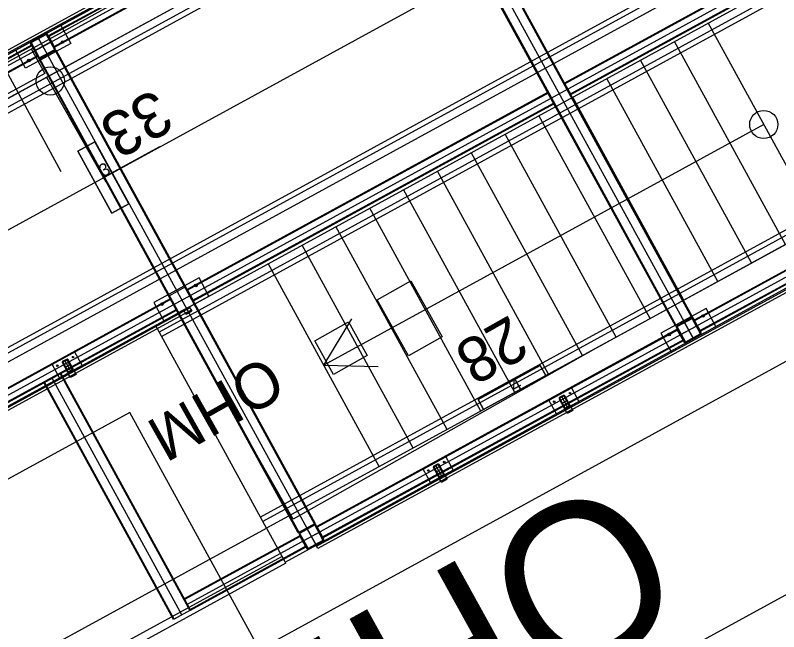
# Model space of a CAD drawing. Extents: x -783978 to -783565, y -1064821 to -1064596.
# Drawn here: x -783747.19 to -783741.25, y -1064675.51 to -1064670.72 of the extents above; entities that cross this region are included whole.
import ezdxf

# ---------------------------------------------------------------- set-up
doc = ezdxf.new("R2010")
doc.units = 0
for name, color, linetype in [('Default', 7, 'Continuous'), ('SO 01_20_01', 7, 'Continuous'), ('SO 01_50_01', 7, 'Continuous'), ('SO 01_74_01', 7, 'Continuous'), ('SO 01_77_01', 7, 'Continuous'), ('SO 01_79_02', 7, 'Continuous'), ('SO 01_86_04', 7, 'Continuous')]:
    doc.layers.add(name, color=color, linetype=linetype)

# ---------------------------------------------------------------- blocks, each defined once
blk = doc.blocks.new('POINT_DISPLAY')
at = {"layer": 'Default'}
blk.add_line((0, 0), (0, 0), dxfattribs=at)

msp = doc.modelspace()

# ---------------------------------------------------------------- linework, layer by layer
at = {"layer": 'SO 01_20_01'}
for p, q in [((-783735.2041, -1064664.4318), (-783786.7885, -1064692.6541)), ((-783786.6445, -1064692.9173), (-783735.3233, -1064664.839)), ((-783738.0171, -1064666.3812), (-783786.4402, -1064692.874)), ((-783786.421, -1064692.9091), (-783737.9979, -1064666.4163)), ((-783737.8741, -1064667.2605), (-783785.3352, -1064693.2269)), ((-783785.6531, -1064694.3127), (-783737.23, -1064667.82)), ((-783737.0912, -1064667.858), (-783785.7805, -1064694.4964)), ((-783737.2108, -1064667.855), (-783785.6339, -1064694.3478)), ((-783785.6366, -1064694.7596), (-783736.9472, -1064668.1212)), ((-783737.0092, -1064668.2235), (-783746.0685, -1064673.1799)), ((-783746.0493, -1064673.215), (-783736.99, -1064668.2586)), ((-783733.4514, -1064668.2604), (-783745.2333, -1064674.7064)), ((-783745.0893, -1064674.9696), (-783733.0442, -1064668.3796)), ((-783745.2813, -1064674.6187), (-783736.222, -1064669.6623)), ((-783736.2028, -1064669.6973), (-783745.2621, -1064674.6538)), ((-783736.4011, -1064670.7861), (-783745.288, -1064675.6482)), ((-783740.9346, -1064672.3546), (-783741.7986, -1064670.7754)), ((-783741.1978, -1064672.4985), (-783742.0618, -1064670.9194)), ((-783741.461, -1064672.6425), (-783742.325, -1064671.0634)), ((-783741.7242, -1064672.7865), (-783742.5881, -1064671.2074)), ((-783741.9874, -1064672.9305), (-783742.8513, -1064671.3514)), ((-783742.2506, -1064673.0745), (-783743.1145, -1064671.4954)), ((-783741.3666, -1064671.565), (-783744.788, -1064673.4369)), ((-783742.5138, -1064673.2185), (-783743.3777, -1064671.6394)), ((-783742.7769, -1064673.3625), (-783743.6409, -1064671.7834)), ((-783743.0401, -1064673.5065), (-783743.9041, -1064671.9274)), ((-783743.3033, -1064673.6505), (-783744.1673, -1064672.0714)), ((-783743.5665, -1064673.7945), (-783744.4304, -1064672.2154)), ((-783743.8297, -1064673.9385), (-783744.6936, -1064672.3593)), ((-783744.0929, -1064674.0825), (-783744.9568, -1064672.5033)), ((-783744.3561, -1064674.2264), (-783745.22, -1064672.6473)), ((-783744.788, -1064673.4369), (-783744.5685, -1064673.076)), ((-783745.2333, -1064674.7064), (-783746.0973, -1064673.1273)), ((-783744.788, -1064673.4369), (-783744.3657, -1064673.4466)), ((-783746.2961, -1064673.8055), (-783785.8354, -1064695.4379)), ((-783745.288, -1064675.6482), (-783746.2961, -1064673.8055)), ((-783745.2333, -1064674.7064), (-783745.0893, -1064674.9696))]:
    msp.add_line(p, q, dxfattribs=at)
msp.add_circle((-783741.3666, -1064671.565), 0.1095, dxfattribs=at)
at = {"layer": 'SO 01_50_01'}
for p, q in [((-783786.7885, -1064692.6541), (-783725.4827, -1064659.1131)), ((-783747.3107, -1064671.0555), (-783742.9243, -1064668.6556)), ((-783747.3106, -1064671.0555), (-783742.9242, -1064668.6557)), ((-783747.3106, -1064671.0555), (-783742.9242, -1064668.6557)), ((-783746.8307, -1064671.9327), (-783747.7907, -1064670.1782))]:
    msp.add_line(p, q, dxfattribs=at)
for points in [[(-783783.6289, -1064698.4393), (-783735.7029, -1064672.2185)], [(-783784.7751, -1064696.3401), (-783745.2333, -1064674.7064)], [(-783784.6553, -1064696.5595), (-783745.1133, -1064674.9257)]]:
    msp.add_lwpolyline(points, dxfattribs=at)
at = {"layer": 'SO 01_74_01'}
for p, q in [((-783735.2185, -1064664.4055), (-783786.6099, -1064692.5222)), ((-783786.6003, -1064692.5398), (-783735.2089, -1064664.423)), ((-783744.8433, -1064674.8464), (-783733.0394, -1064668.3884)), ((-783733.0298, -1064668.4059), (-783744.8337, -1064674.8639)), ((-783744.1272, -1064669.3423), (-783746.93, -1064670.8757)), ((-783744.1242, -1064669.3478), (-783746.927, -1064670.8812)), ((-783746.8851, -1064670.9579), (-783744.0823, -1064669.4245)), ((-783746.882, -1064670.9634), (-783744.0792, -1064669.43)), ((-783743.9427, -1064669.3838), (-783741.9268, -1064673.0684)), ((-783743.9357, -1064669.3799), (-783741.9198, -1064673.0645)), ((-783742.0514, -1064673.1365), (-783744.0672, -1064669.4519)), ((-783742.0443, -1064673.1327), (-783744.0602, -1064669.4481)), ((-783740.1128, -1064669.7106), (-783742.9156, -1064671.2441)), ((-783740.1098, -1064669.7162), (-783742.9126, -1064671.2496)), ((-783742.8706, -1064671.3263), (-783740.0678, -1064669.7928)), ((-783742.8676, -1064671.3318), (-783740.0648, -1064669.7984)), ((-783746.93, -1064670.8757), (-783746.882, -1064670.9634)), ((-783746.927, -1064670.8812), (-783746.8851, -1064670.9579)), ((-783747.0618, -1064670.9478), (-783749.6278, -1064672.3517)), ((-783747.0587, -1064670.9533), (-783749.6248, -1064672.3572)), ((-783747.0138, -1064671.0355), (-783747.0618, -1064670.9478)), ((-783747.0168, -1064671.03), (-783747.0587, -1064670.9533)), ((-783749.5828, -1064672.4339), (-783747.0168, -1064671.03)), ((-783749.5798, -1064672.4394), (-783747.0138, -1064671.0355)), ((-783747.0018, -1064671.0574), (-783746.8702, -1064670.9854)), ((-783746.9947, -1064671.0536), (-783746.8772, -1064670.9893)), ((-783746.8772, -1064670.9893), (-783744.8613, -1064674.6739)), ((-783746.8702, -1064670.9854), (-783744.8543, -1064674.67)), ((-783744.9859, -1064674.742), (-783747.0018, -1064671.0574)), ((-783744.9789, -1064674.7382), (-783746.9947, -1064671.0536)), ((-783742.9156, -1064671.2441), (-783742.8676, -1064671.3318)), ((-783742.9126, -1064671.2496), (-783742.8706, -1064671.3263)), ((-783743.0473, -1064671.3161), (-783745.8501, -1064672.8496)), ((-783743.0443, -1064671.3217), (-783745.8471, -1064672.8551)), ((-783742.9993, -1064671.4039), (-783743.0473, -1064671.3161)), ((-783743.0023, -1064671.3983), (-783743.0443, -1064671.3217)), ((-783745.8051, -1064672.9318), (-783743.0023, -1064671.3983)), ((-783745.8021, -1064672.9373), (-783742.9993, -1064671.4039)), ((-783739.1048, -1064671.5529), (-783741.9076, -1064673.0864)), ((-783739.1018, -1064671.5585), (-783741.9046, -1064673.0919)), ((-783741.8627, -1064673.1686), (-783739.0599, -1064671.6351)), ((-783741.8596, -1064673.1741), (-783739.0569, -1064671.6407)), ((-783745.8622, -1064672.8277), (-783745.9938, -1064672.8997)), ((-783745.7902, -1064672.9593), (-783745.8622, -1064672.8277)), ((-783745.8501, -1064672.8496), (-783745.8021, -1064672.9373)), ((-783745.8471, -1064672.8551), (-783745.8051, -1064672.9318)), ((-783745.9818, -1064672.9216), (-783748.5479, -1064674.3256)), ((-783745.9788, -1064672.9272), (-783748.5449, -1064674.3311)), ((-783745.9938, -1064672.8997), (-783745.9218, -1064673.0313)), ((-783745.9338, -1064673.0094), (-783745.9818, -1064672.9216)), ((-783745.9368, -1064673.0038), (-783745.9788, -1064672.9272)), ((-783785.4388, -1064694.6628), (-783745.8293, -1064672.9921)), ((-783745.9218, -1064673.0313), (-783745.7902, -1064672.9593)), ((-783745.878, -1064673.0073), (-783745.8341, -1064672.9833)), ((-783745.8341, -1064672.9833), (-783745.8149, -1064673.0184)), ((-783745.8293, -1064672.9921), (-783745.8197, -1064673.0096)), ((-783745.8197, -1064673.0096), (-783785.4292, -1064694.6803)), ((-783748.5029, -1064674.4078), (-783745.9368, -1064673.0038)), ((-783748.4999, -1064674.4133), (-783745.9338, -1064673.0094)), ((-783745.8588, -1064673.0424), (-783745.878, -1064673.0073)), ((-783745.8149, -1064673.0184), (-783745.8588, -1064673.0424)), ((-783741.9198, -1064673.0645), (-783742.0514, -1064673.1365)), ((-783741.9268, -1064673.0684), (-783742.0443, -1064673.1327)), ((-783741.9076, -1064673.0864), (-783741.8596, -1064673.1741)), ((-783741.9046, -1064673.0919), (-783741.8627, -1064673.1686)), ((-783742.0394, -1064673.1584), (-783744.8422, -1064674.6919)), ((-783742.0363, -1064673.164), (-783744.8391, -1064674.6974)), ((-783741.9914, -1064673.2462), (-783742.0394, -1064673.1584)), ((-783741.9944, -1064673.2406), (-783742.0363, -1064673.164)), ((-783744.7972, -1064674.7741), (-783741.9944, -1064673.2406)), ((-783744.7942, -1064674.7796), (-783741.9914, -1064673.2462)), ((-783746.7772, -1064673.4993), (-783746.7333, -1064673.4753)), ((-783746.7333, -1064673.4753), (-783746.7141, -1064673.5104)), ((-783746.9646, -1064673.5733), (-783746.833, -1064673.5013)), ((-783746.9591, -1064673.5703), (-783746.8386, -1064673.5044)), ((-783746.8386, -1064673.5044), (-783745.8306, -1064675.3467)), ((-783746.833, -1064673.5013), (-783745.8251, -1064675.3436)), ((-783746.758, -1064673.5344), (-783746.7772, -1064673.4993)), ((-783746.7724, -1064673.5081), (-783746.7285, -1064673.4841)), ((-783746.7628, -1064673.5256), (-783746.7724, -1064673.5081)), ((-783746.7189, -1064673.5016), (-783746.7628, -1064673.5256)), ((-783746.7141, -1064673.5104), (-783746.758, -1064673.5344)), ((-783746.7285, -1064673.4841), (-783746.7189, -1064673.5016)), ((-783745.9567, -1064675.4156), (-783746.9646, -1064673.5733)), ((-783745.9512, -1064675.4126), (-783746.9591, -1064673.5703)), ((-783742.9137, -1064673.7793), (-783742.8698, -1064673.7553)), ((-783742.9089, -1064673.788), (-783742.865, -1064673.764)), ((-783742.8698, -1064673.7553), (-783742.8506, -1064673.7904)), ((-783742.865, -1064673.764), (-783742.8554, -1064673.7816)), ((-783742.8945, -1064673.8144), (-783742.9137, -1064673.7793)), ((-783742.8993, -1064673.8056), (-783742.9089, -1064673.788)), ((-783742.8554, -1064673.7816), (-783742.8993, -1064673.8056)), ((-783742.8506, -1064673.7904), (-783742.8945, -1064673.8144)), ((-783743.8919, -1064674.3144), (-783743.848, -1064674.2904)), ((-783743.8871, -1064674.3232), (-783743.8432, -1064674.2992)), ((-783743.848, -1064674.2904), (-783743.8288, -1064674.3255)), ((-783743.8432, -1064674.2992), (-783743.8336, -1064674.3168)), ((-783743.8727, -1064674.3495), (-783743.8919, -1064674.3144)), ((-783743.8775, -1064674.3408), (-783743.8871, -1064674.3232)), ((-783743.8336, -1064674.3168), (-783743.8775, -1064674.3408)), ((-783743.8288, -1064674.3255), (-783743.8727, -1064674.3495)), ((-783744.8543, -1064674.67), (-783744.9859, -1064674.742)), ((-783744.8613, -1064674.6739), (-783744.9789, -1064674.7382)), ((-783744.8422, -1064674.6919), (-783744.7942, -1064674.7796)), ((-783744.8391, -1064674.6974), (-783744.7972, -1064674.7741)), ((-783744.9739, -1064674.7639), (-783745.8731, -1064675.2559)), ((-783744.9709, -1064674.7695), (-783745.8701, -1064675.2614)), ((-783744.9259, -1064674.8517), (-783744.9739, -1064674.7639)), ((-783744.9289, -1064674.8461), (-783744.9709, -1064674.7695)), ((-783745.8281, -1064675.3381), (-783744.9289, -1064674.8461)), ((-783745.8251, -1064675.3436), (-783744.9259, -1064674.8517)), ((-783744.8337, -1064674.8639), (-783744.8433, -1064674.8464)), ((-783745.8731, -1064675.2559), (-783745.8251, -1064675.3436)), ((-783745.8701, -1064675.2614), (-783745.8281, -1064675.3381)), ((-783745.8251, -1064675.3436), (-783745.9567, -1064675.4156)), ((-783745.8306, -1064675.3467), (-783745.9512, -1064675.4126))]:
    msp.add_line(p, q, dxfattribs=at)
for points in [[(-783735.1681, -1064664.4976), (-783787.4762, -1064693.1159)], [(-783734.0882, -1064666.4715), (-783786.3963, -1064695.0898)], [(-783733.0802, -1064668.3138), (-783745.8491, -1064675.2998)], [(-783744.0734, -1064669.2843), (-783741.9136, -1064673.2321)], [(-783746.9527, -1064670.8596), (-783747.0632, -1064670.9201)], [(-783746.9488, -1064670.8666), (-783747.0594, -1064670.9271)], [(-783746.9062, -1064670.9196), (-783747.0378, -1064670.9916)], [(-783747.008, -1064670.8898), (-783744.8481, -1064674.8376)], [(-783746.936, -1064671.0214), (-783747.008, -1064670.8898)], [(-783746.8829, -1064670.9787), (-783746.9434, -1064670.8682)], [(-783746.8759, -1064670.9749), (-783746.9364, -1064670.8644)], [(-783747.068, -1064670.9364), (-783747.0075, -1064671.0469)], [(-783747.061, -1064670.9325), (-783747.0005, -1064671.0431)], [(-783746.9951, -1064671.0446), (-783746.8845, -1064670.9842)], [(-783746.9912, -1064671.0517), (-783746.8807, -1064670.9912)], [(-783741.9303, -1064673.0703), (-783742.0408, -1064673.1308)], [(-783741.9265, -1064673.0773), (-783742.037, -1064673.1378)], [(-783741.9136, -1064673.2321), (-783741.9856, -1064673.1005)], [(-783741.8606, -1064673.1894), (-783741.921, -1064673.0789)], [(-783741.8535, -1064673.1856), (-783741.914, -1064673.075)], [(-783742.0456, -1064673.147), (-783741.9851, -1064673.2576)], [(-783742.0386, -1064673.1432), (-783741.9781, -1064673.2537)], [(-783741.8838, -1064673.1303), (-783742.0154, -1064673.2023)], [(-783741.9727, -1064673.2553), (-783741.8621, -1064673.1948)], [(-783741.9688, -1064673.2623), (-783741.8583, -1064673.2019)], [(-783746.7896, -1064673.3921), (-783746.8169, -1064673.407)], [(-783746.7866, -1064673.3976), (-783746.8139, -1064673.4125)], [(-783746.8032, -1064673.3996), (-783746.7552, -1064673.4873)], [(-783746.7434, -1064673.47), (-783746.7823, -1064673.3989)], [(-783746.7378, -1064673.467), (-783746.7768, -1064673.3958)], [(-783746.8206, -1064673.4198), (-783746.7817, -1064673.491)], [(-783746.8151, -1064673.4168), (-783746.7762, -1064673.488)], [(-783746.7573, -1064673.4314), (-783746.8012, -1064673.4554)], [(-783746.7719, -1064673.4892), (-783746.7446, -1064673.4743)], [(-783746.7689, -1064673.4947), (-783746.7416, -1064673.4798)], [(-783745.8909, -1064675.3796), (-783746.8988, -1064673.5373)], [(-783742.9571, -1064673.6998), (-783742.9182, -1064673.771)], [(-783742.9261, -1064673.6721), (-783742.9534, -1064673.687)], [(-783742.9516, -1064673.6968), (-783742.9127, -1064673.768)], [(-783742.9231, -1064673.6776), (-783742.9504, -1064673.6925)], [(-783742.9397, -1064673.6795), (-783742.8917, -1064673.7673)], [(-783742.8938, -1064673.7114), (-783742.9377, -1064673.7354)], [(-783742.8799, -1064673.75), (-783742.9188, -1064673.6789)], [(-783742.8743, -1064673.747), (-783742.9133, -1064673.6758)], [(-783742.9084, -1064673.7692), (-783742.8811, -1064673.7543)], [(-783742.9054, -1064673.7747), (-783742.8781, -1064673.7598)], [(-783743.9353, -1064674.235), (-783743.8964, -1064674.3061)], [(-783743.9043, -1064674.2072), (-783743.9316, -1064674.2222)], [(-783743.9298, -1064674.232), (-783743.8909, -1064674.3031)], [(-783743.9012, -1064674.2128), (-783743.9285, -1064674.2277)], [(-783743.9179, -1064674.2147), (-783743.8699, -1064674.3024)], [(-783743.872, -1064674.2466), (-783743.9158, -1064674.2706)], [(-783743.858, -1064674.2852), (-783743.897, -1064674.214)], [(-783743.8525, -1064674.2822), (-783743.8914, -1064674.211)], [(-783743.8866, -1064674.3044), (-783743.8593, -1064674.2895)], [(-783743.8836, -1064674.3099), (-783743.8563, -1064674.295)], [(-783744.8648, -1064674.6758), (-783744.9754, -1064674.7363)], [(-783744.861, -1064674.6828), (-783744.9715, -1064674.7433)], [(-783744.8481, -1064674.8376), (-783744.9201, -1064674.706)], [(-783744.7951, -1064674.7949), (-783744.8555, -1064674.6844)], [(-783744.7881, -1064674.7911), (-783744.8485, -1064674.6805)], [(-783744.9801, -1064674.7525), (-783744.9196, -1064674.8631)], [(-783744.9731, -1064674.7487), (-783744.9126, -1064674.8592)], [(-783744.8183, -1064674.7358), (-783744.9499, -1064674.8078)], [(-783744.9072, -1064674.8608), (-783744.7967, -1064674.8004)], [(-783744.9034, -1064674.8678), (-783744.7928, -1064674.8074)]]:
    msp.add_lwpolyline(points, dxfattribs=at)
for points in [[(-783746.7557, -1064670.9342), (-783747.1066, -1064671.1262), (-783747.1834, -1064670.9858), (-783746.8325, -1064670.7938)], [(-783745.7574, -1064672.759), (-783746.1083, -1064672.9509), (-783746.0315, -1064673.0913), (-783745.6806, -1064672.8993)], [(-783741.8149, -1064672.9957), (-783742.1658, -1064673.1877), (-783742.089, -1064673.3281), (-783741.7381, -1064673.1361)], [(-783746.6675, -1064673.4393), (-783746.843, -1064673.5353), (-783746.9006, -1064673.43), (-783746.7251, -1064673.334)], [(-783742.804, -1064673.7193), (-783742.9795, -1064673.8153), (-783743.0371, -1064673.71), (-783742.8616, -1064673.614)], [(-783743.7822, -1064674.2544), (-783743.9576, -1064674.3504), (-783744.0152, -1064674.2452), (-783743.8398, -1064674.1492)]]:
    msp.add_lwpolyline(points, close=True, dxfattribs=at)
for centre, radius in [((-783746.8188, -1064670.9231), 0.01), ((-783747.082, -1064671.0671), 0.01), ((-783745.782, -1064672.818), 0.01), ((-783746.0452, -1064672.962), 0.01), ((-783741.8396, -1064673.0548), 0.01), ((-783742.1028, -1064673.1988), 0.01), ((-783746.737, -1064673.3747), 0.006), ((-783746.8599, -1064673.4419), 0.006), ((-783742.8735, -1064673.6547), 0.006), ((-783742.9964, -1064673.7219), 0.006), ((-783743.8517, -1064674.1899), 0.006), ((-783743.9745, -1064674.2571), 0.006)]:
    msp.add_circle(centre, radius, dxfattribs=at)
for centre, radius, start, end in [((-783746.9469, -1064670.8701), 0.012, 28.68349, 118.68349), ((-783747.0575, -1064670.9306), 0.012, 118.68349, 208.68349), ((-783746.9469, -1064670.8701), 0.004, 28.68349, 118.68349), ((-783747.0575, -1064670.9306), 0.004, 118.68349, 208.68349), ((-783746.8865, -1064670.9807), 0.004, 298.68349, 28.68349), ((-783746.8865, -1064670.9807), 0.012, 298.68349, 28.68349), ((-783746.997, -1064671.0411), 0.012, 208.68349, 298.68349), ((-783746.997, -1064671.0411), 0.004, 208.68349, 298.68349), ((-783741.9245, -1064673.0808), 0.012, 28.68349, 118.68349), ((-783741.9245, -1064673.0808), 0.004, 28.68349, 118.68349), ((-783742.0351, -1064673.1413), 0.012, 118.68349, 208.68349), ((-783742.0351, -1064673.1413), 0.004, 118.68349, 208.68349), ((-783741.8641, -1064673.1913), 0.004, 298.68349, 28.68349), ((-783741.8641, -1064673.1913), 0.012, 298.68349, 28.68349), ((-783741.9746, -1064673.2518), 0.012, 208.68349, 298.68349), ((-783741.9746, -1064673.2518), 0.004, 208.68349, 298.68349), ((-783746.8123, -1064673.4153), 0.00945, 118.68349, 208.68349), ((-783746.8123, -1064673.4153), 0.00315, 118.68349, 208.68349), ((-783746.7851, -1064673.4004), 0.00945, 28.68349, 118.68349), ((-783746.7851, -1064673.4004), 0.00315, 28.68349, 118.68349), ((-783746.7461, -1064673.4715), 0.00315, 298.68349, 28.68349), ((-783746.7461, -1064673.4715), 0.00945, 298.68349, 28.68349), ((-783746.7734, -1064673.4865), 0.00945, 208.68349, 298.68349), ((-783746.7734, -1064673.4865), 0.00315, 208.68349, 298.68349), ((-783742.9488, -1064673.6953), 0.00945, 118.68349, 208.68349), ((-783742.9488, -1064673.6953), 0.00315, 118.68349, 208.68349), ((-783742.9216, -1064673.6804), 0.00945, 28.68349, 118.68349), ((-783742.9216, -1064673.6804), 0.00315, 28.68349, 118.68349), ((-783742.9099, -1064673.7664), 0.00945, 208.68349, 298.68349), ((-783742.9099, -1064673.7664), 0.00315, 208.68349, 298.68349), ((-783742.8826, -1064673.7515), 0.00315, 298.68349, 28.68349), ((-783742.8826, -1064673.7515), 0.00945, 298.68349, 28.68349), ((-783743.927, -1064674.2305), 0.00945, 118.68349, 208.68349), ((-783743.927, -1064674.2305), 0.00315, 118.68349, 208.68349), ((-783743.8997, -1064674.2155), 0.00945, 28.68349, 118.68349), ((-783743.8997, -1064674.2155), 0.00315, 28.68349, 118.68349), ((-783743.8881, -1064674.3016), 0.00945, 208.68349, 298.68349), ((-783743.8881, -1064674.3016), 0.00315, 208.68349, 298.68349), ((-783743.8608, -1064674.2867), 0.00315, 298.68349, 28.68349), ((-783743.8608, -1064674.2867), 0.00945, 298.68349, 28.68349), ((-783744.8591, -1064674.6863), 0.012, 28.68349, 118.68349), ((-783744.8591, -1064674.6863), 0.004, 28.68349, 118.68349), ((-783744.9696, -1064674.7468), 0.012, 118.68349, 208.68349), ((-783744.9696, -1064674.7468), 0.004, 118.68349, 208.68349), ((-783744.7986, -1064674.7968), 0.004, 298.68349, 28.68349), ((-783744.7986, -1064674.7968), 0.012, 298.68349, 28.68349), ((-783744.9091, -1064674.8573), 0.012, 208.68349, 298.68349), ((-783744.9091, -1064674.8573), 0.004, 208.68349, 298.68349)]:
    msp.add_arc(centre, radius, start, end, dxfattribs=at)
at = {"layer": 'SO 01_77_01'}
for points in [[(-783744.1288, -1064673.365), (-783744.3737, -1064672.9291), (-783744.1121, -1064672.7821), (-783743.8673, -1064673.2181)], [(-783744.8583, -1064673.2473), (-783744.5967, -1064673.1003), (-783744.4498, -1064673.3619), (-783744.7114, -1064673.5088)]]:
    msp.add_lwpolyline(points, close=True, dxfattribs=at)
at = {"layer": 'SO 01_79_02'}
msp.add_lwpolyline([(-783745.0819, -1064674.9774), (-783746.507, -1064675.7571), (-783748.1468, -1064676.6636), (-783749.6912, -1064678.1356), (-783784.2571, -1064697.0125), (-783798.19, -1064704.62), (-783800.06, -1064705.37), (-783802.52, -1064706.72), (-783803.71, -1064707.63), (-783853.11, -1064734.61), (-783855.1, -1064735.3), (-783857.05, -1064736.37), (-783858.65, -1064737.64), (-783871.68, -1064744.75), (-783877.0563, -1064744.607), (-783887.4289, -1064744.0617), (-783898.0887, -1064743.4896), (-783899.4205, -1064743.4179)], dxfattribs=at)
at = {"layer": 'SO 01_86_04'}
for p, q in [((-783746.9432, -1064671.1964), (-783746.483, -1064672.011)), ((-783746.5687, -1064671.7001), (-783746.7003, -1064671.7721)), ((-783746.5687, -1064671.7001), (-783746.7003, -1064671.7721)), ((-783746.7003, -1064671.7721), (-783746.5687, -1064671.7001)), ((-783746.7003, -1064671.7721), (-783746.5687, -1064671.7001)), ((-783746.3047, -1064672.1826), (-783746.5687, -1064671.7001)), ((-783746.3047, -1064672.1826), (-783746.5687, -1064671.7001)), ((-783746.5687, -1064671.7001), (-783746.3047, -1064672.1826)), ((-783746.5687, -1064671.7001), (-783746.3047, -1064672.1826)), ((-783746.5025, -1064671.9774), (-783746.0638, -1064671.7374)), ((-783746.7003, -1064671.7721), (-783746.4363, -1064672.2546)), ((-783746.7003, -1064671.7721), (-783746.4363, -1064672.2546)), ((-783746.4363, -1064672.2546), (-783746.7003, -1064671.7721)), ((-783746.4363, -1064672.2546), (-783746.7003, -1064671.7721)), ((-783746.4363, -1064672.2546), (-783746.3047, -1064672.1826)), ((-783746.4363, -1064672.2546), (-783746.3047, -1064672.1826)), ((-783746.3047, -1064672.1826), (-783746.4363, -1064672.2546)), ((-783746.3047, -1064672.1826), (-783746.4363, -1064672.2546)), ((-783743.1053, -1064673.4395), (-783743.5878, -1064673.7035)), ((-783743.5878, -1064673.7035), (-783743.1053, -1064673.4395)), ((-783743.5878, -1064673.7035), (-783743.1053, -1064673.4395)), ((-783743.1053, -1064673.4395), (-783743.5878, -1064673.7035)), ((-783743.0621, -1064673.5185), (-783743.1053, -1064673.4395)), ((-783743.1053, -1064673.4395), (-783743.0621, -1064673.5185)), ((-783743.0621, -1064673.5185), (-783743.1053, -1064673.4395)), ((-783743.1053, -1064673.4395), (-783743.0621, -1064673.5185)), ((-783743.5446, -1064673.7825), (-783743.0621, -1064673.5185)), ((-783743.0621, -1064673.5185), (-783743.5446, -1064673.7825)), ((-783743.5446, -1064673.7825), (-783743.0621, -1064673.5185)), ((-783743.0621, -1064673.5185), (-783743.5446, -1064673.7825)), ((-783743.5878, -1064673.7035), (-783743.5446, -1064673.7825)), ((-783743.5446, -1064673.7825), (-783743.5878, -1064673.7035)), ((-783743.5878, -1064673.7035), (-783743.5446, -1064673.7825)), ((-783743.5446, -1064673.7825), (-783743.5878, -1064673.7035))]:
    msp.add_line(p, q, dxfattribs=at)
for points in [[(-783735.4626, -1064664.5844), (-783749.7616, -1064672.4637), (-783749.643, -1064672.6735)], [(-783738.3222, -1064666.4797), (-783740.5325, -1064667.689), (-783743.1715, -1064669.1328), (-783745.7538, -1064670.5456), (-783748.4385, -1064672.0145), (-783751.0413, -1064673.4385), (-783753.6847, -1064674.8847), (-783756.3281, -1064676.3309), (-783758.9715, -1064677.7772), (-783761.6149, -1064679.2234), (-783764.2583, -1064680.6696), (-783766.9018, -1064682.1159), (-783769.4633, -1064683.5173), (-783772.109, -1064684.9648), (-783774.7882, -1064686.4306), (-783778.1382, -1064688.2722), (-783783.8139, -1064691.3971), (-783785.747, -1064692.4898)], [(-783733.4229, -1064668.3125), (-783737.6471, -1064670.5617), (-783739.9521, -1064671.817), (-783742.6942, -1064673.3169), (-783745.0268, -1064674.6345), (-783745.4136, -1064673.9496)], [(-783747.063, -1064670.9765), (-783746.9575, -1064671.1681), (-783786.6893, -1064692.8619), (-783786.185, -1064693.7636)]]:
    msp.add_lwpolyline(points, dxfattribs=at)
msp.add_circle((-783746.9148, -1064671.2265), 0.1097, dxfattribs=at)

# ---------------------------------------------------------------- block references
at = {"layer": 'SO 01_86_04', "xscale": 0.010000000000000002, "yscale": 0.009999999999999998, "rotation": 28.683491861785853}
for p in [(-783746.5687, -1064671.7001), (-783746.5687, -1064671.7001), (-783746.7003, -1064671.7721), (-783746.7003, -1064671.7721), (-783746.3047, -1064672.1826), (-783746.3047, -1064672.1826), (-783746.4363, -1064672.2546), (-783746.4363, -1064672.2546), (-783743.1053, -1064673.4395), (-783743.1053, -1064673.4395), (-783743.0621, -1064673.5185), (-783743.0621, -1064673.5185), (-783743.3465, -1064673.5715), (-783743.5878, -1064673.7035), (-783743.5878, -1064673.7035), (-783743.5446, -1064673.7825), (-783743.5446, -1064673.7825)]:
    msp.add_blockref('POINT_DISPLAY', p, dxfattribs=at)

# ---------------------------------------------------------------- texts
at = {"layer": 'SO 01_77_01'}
msp.add_text('OHM1', height=1.25, rotation=208.91069, dxfattribs=at).set_placement((-783742.5114, -1064674.2647))
at = {"layer": 'SO 01_86_04'}
for s, height, rotation, p in [('33', 0.351, 209.46001, (-783746.1, -1064671.2799)), ('3', 0.1, 28.68349, (-783746.5025, -1064671.9774)), ('28', 0.351, 209.46001, (-783743.3382, -1064673.0414)), ('OHM', 0.351, 209.46001, (-783745.2333, -1064673.3551)), ('4', 0.1, 28.68349, (-783743.3033, -1064673.6505))]:
    msp.add_text(s, height=height, rotation=rotation, dxfattribs=at).set_placement(p)

doc.saveas('drawing.dxf')
